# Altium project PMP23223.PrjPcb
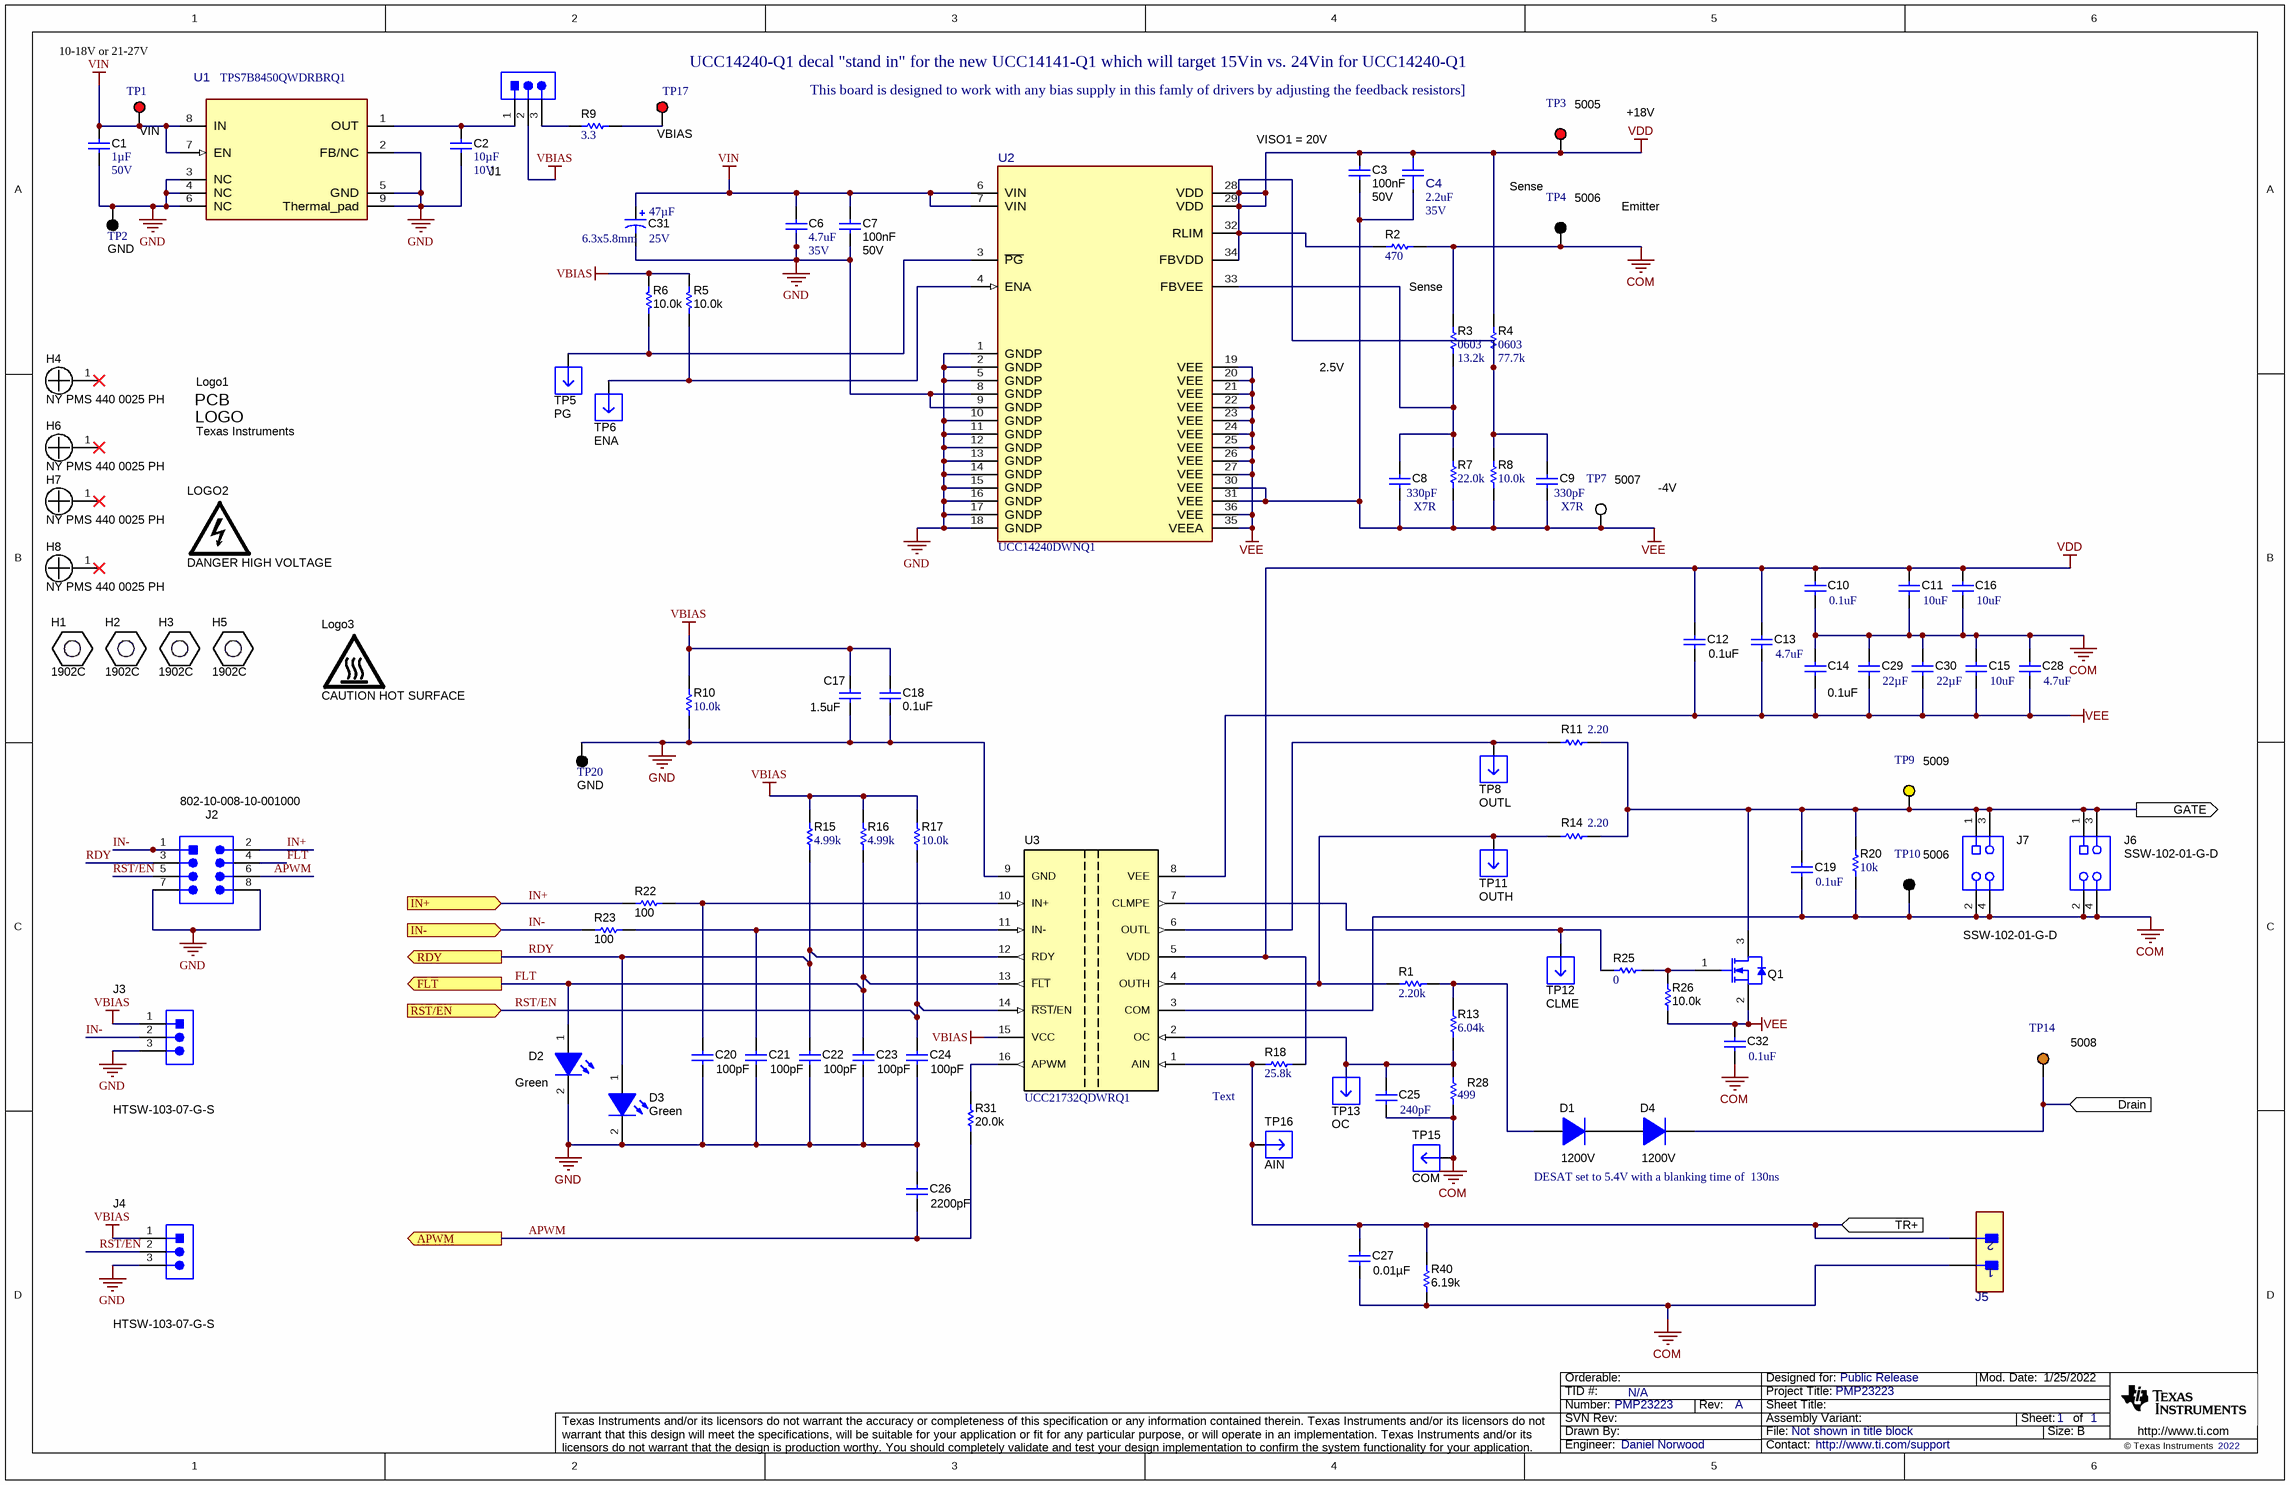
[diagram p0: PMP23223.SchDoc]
CopyrightYear: 2022; PCB_Layout: Daniel Norwood; PCB_Rev: E1; PRJ_Customer: Public Release; PRJ_Engineer: Daniel Norwood; PRJ_Number: PMP23223; PRJ_Title: PMP23223; SCH_Rev: A; TechSupport: http://www.ti.com/support; TID: N/A
2 sheets, 100 parts. Net scope: flat (ports and power ports of the same name join across sheets).
Board file: PMP23223.PcbDoc
Sheets:
  Block Diagram.SchDoc
  PMP23223.SchDoc

## Sheet Block Diagram.SchDoc
size A2; Date: Not shown in title block; ApprovedBy: Not shown in title block; CheckedBy: Not shown in title block; Author: Not shown in title block; CompanyName: Not shown in title block; Engineer: Not shown in title block; Organization: Not shown in title block; Address1: Not shown in title block; Address2: Not shown in title block; Address3: Not shown in title block; Address4: Not shown in title block; DocumentNumber: 1; Revision: Use project parameter SCH_Rev; SheetNumber: 2; SheetTotal: 2; PageSetup: Record=PageOptions¦CenterHorizontal=True¦CenterVertical=True¦PrintScale=0.69¦XCorrection=1.00¦YCorrection=1.00¦PrintKind=0¦BorderSize=5000000¦LeftOffset=0¦BottomOffset=0¦Orientation=2¦PaperLength=1000¦PaperWidth=1000¦Scale=100¦PaperSource=15¦PrintQuality=600¦MediaType=1¦DitherType=10¦PaperKind=Letter¦PrintScaleMode=1

## Sheet PMP23223.SchDoc
size 431 x 279 mm; Date: Not shown in title block; ApprovedBy: Not shown in title block; CheckedBy: Not shown in title block; Author: Not shown in title block; CompanyName: Not shown in title block; Engineer: Not shown in title block; Organization: Not shown in title block; Address1: Not shown in title block; Address2: Not shown in title block; Address3: Not shown in title block; Address4: Not shown in title block; DocumentNumber: 2; Revision: Use project parameter SCH_Rev; SheetNumber: 1; SheetTotal: 1; PageSetup: Record=PageOptions¦CenterHorizontal=True¦CenterVertical=True¦PrintScale=1.00¦XCorrection=1.00¦YCorrection=1.00¦PrintKind=0¦BorderSize=5000000¦LeftOffset=0¦BottomOffset=0¦Orientation=2¦PaperLength=1000¦PaperWidth=1000¦Scale=100¦PaperSource=15¦PrintQuality=600¦MediaType=1¦DitherType=10¦PaperKind=Letter¦PrintScaleMode=1

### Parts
C1  Cap_F: 1µF  VDC_V: 50V  [0805_HV]  (hidden comment: CGA4J3X7R1H105K125AB)
C2  Cap_F: 10µF  VDC_V: 10V  [0805_HV]  (hidden comment: GCJ21BR71A106KE01L)
C3  Cap_F: 100nF  VDC_V: 50V  [0603]  (hidden comment: CGA3E2X7R1H104K080AA)
C4  ValueDisplayed: 2.2uF  VDC_V: 35V  [FP-GRT188C8YA225KE13D_0603-MFG]  (hidden comment: GRT188C8YA225KE13D)
C6  ValueDisplayed: 4.7uF  VDC_V: 35V  [0805_HV]  (hidden comment: CGA4J1X7R1V475K125AC)
C7  Cap_F: 100nF  VDC_V: 50V  [0603]  (hidden comment: CGA3E2X7R1H104K080AA)
C8  TempCo: X7R  Cap_F: 330pF  [0603]  (hidden comment: GRM188R72A331KA01D)
C9  TempCo: X7R  Cap_F: 330pF  [0603]  (hidden comment: GRM188R72A331KA01D)
C10  ValueDisplayed: 0.1uF  [0402]  (hidden comment: GCM155R71C104KA55D)
C11  ValueDisplayed: 10uF  [1206_180]  (hidden comment: CL31B106KBHNNNE)
C12  ValueDisplayed: 0.1uF  [1206]  (hidden comment: C1206C104J5RACTU)
C13  ValueDisplayed: 4.7uF  [1206_180]  (hidden comment: C3216X7R1H475K160AC)
C14  ValueDisplayed: 0.1uF  [0402]  (hidden comment: GCM155R71C104KA55D)
C15  ValueDisplayed: 10uF  [1206_180]  (hidden comment: CL31B106KBHNNNE)
C16  ValueDisplayed: 10uF  [1206_180]  (hidden comment: CL31B106KBHNNNE)
C17  ValueDisplayed: 1.5uF  [0603]  (hidden comment: C1608X7R1A155K080AC)
C18  ValueDisplayed: 0.1uF  [0402]  (hidden comment: Capacitor)
C19  ValueDisplayed: 0.1uF  [0603]  (hidden comment: C1608X7R1H104K080AA)
C20  ValueDisplayed: 100pF  [0402]  (hidden comment: CC0402JRNPO9BN101)
C21  ValueDisplayed: 100pF  [0402]  (hidden comment: CC0402JRNPO9BN101)
C22  ValueDisplayed: 100pF  [0402]  (hidden comment: CC0402JRNPO9BN101)
C23  ValueDisplayed: 100pF  [0402]  (hidden comment: CC0402JRNPO9BN101)
C24  ValueDisplayed: 100pF  [0402]  (hidden comment: CC0402JRNPO9BN101)
C25  ValueDisplayed: 240pF  [0402]  (hidden comment: GRM1555C1H241JA01D)
C26  ValueDisplayed: 2200pF  [0402]  (hidden comment: GRM155R71C222KA01D)
C27  ValueDisplayed: 0.01µF  [0603]  (hidden comment: SR0603X7R103K1NT95(F)#M123A)
C28  ValueDisplayed: 4.7uF  [1206_180]  (hidden comment: C3216X7R1H475K160AC)
C29  ValueDisplayed: 22µF  [0805_HV]  (hidden comment: GRT21BR61E226ME13L)
C30  ValueDisplayed: 22µF  [0805_HV]  (hidden comment: GRT21BR61E226ME13L)
C31  Cap_Case: 6.3x5.8mm  VDC_V: 25V  ValueDisplayed: 47µF  [HXB_F61]  (hidden comment: HHXC250ARA470MF61G)
C32  ValueDisplayed: 0.1uF  [0603]  (hidden comment: CGA3E2X7R1H104K080AA)
D1  value 1200V  [SMA]  (hidden comment: STTH112A)
D2  value Green  [LG L29K_GREEN]  (hidden comment: LG L29K-G2J1-24-Z)
D3  value Green  [LG L29K_GREEN]  (hidden comment: LG L29K-G2J1-24-Z)
D4  value 1200V  [SMA]  (hidden comment: STTH112A)
H1  1902C  [Keystone_1902C]
H2  1902C  [Keystone_1902C]
H3  1902C  [Keystone_1902C]
H4  NY PMS 440 0025 PH  [NY PMS 440 0025 PH]
H5  1902C  [Keystone_1902C]
H6  NY PMS 440 0025 PH  [NY PMS 440 0025 PH]
H7  NY PMS 440 0025 PH  [NY PMS 440 0025 PH]
H8  NY PMS 440 0025 PH  [NY PMS 440 0025 PH]
J1  HTSW-103-07-G-S  [Samtec_HTSW-103-07-G-S]  (value not drawn)
J2  802-10-008-10-001000  [Mill-Max_802-10-008-10-001000]
J3  HTSW-103-07-G-S  [Samtec_HTSW-103-07-G-S]
J4  HTSW-103-07-G-S  [Samtec_HTSW-103-07-G-S]
J5  2011-1X02G00SB  [FP-2011-1X02G00SB_HDR-MFG]  (value not drawn)
J6  SSW-102-01-G-D  [Samtec_SSW-102-01-x-D]
J7  SSW-102-01-G-D  [Samtec_SSW-102-01-x-D]
Logo1  Texas Instruments  [TI_Symbol_Overlay_Small]  (no BOM)
LOGO2  DANGER HIGH VOLTAGE  [IEC_HighVoltage_Small]  (no BOM)
Logo3  CAUTION HOT SURFACE  [IEC_HotSurface_Small]  (no BOM)
Q1  SI2318CDS-T1-GE3  [SOT-23]  (value not drawn)
R1  ValueDisplayed: 2.20k  [0402]  (hidden comment: RMCF0402FT2K20)
R2  ValueDisplayed: 470  [0603]  (hidden comment: CRCW0603470RJNEA)
R3  ValueDisplayed: 13.2k  [0603]  (hidden comment: RT0603BRD0713K2L)
R4  ValueDisplayed: 77.7k  [0603]  (hidden comment: RT0603DRE0777K7L)
R5  ValueDisplayed: 10.0k  [0603]  (hidden comment: CRCW060310K0FKEA)
R6  ValueDisplayed: 10.0k  [0603]  (hidden comment: CRCW060310K0FKEA)
R7  ValueDisplayed: 22.0k  [0603]  (hidden comment: ERJ-3EKF2202V)
R8  ValueDisplayed: 10.0k  [0603]  (hidden comment: CRCW060310K0FKEA)
R9  ValueDisplayed: 3.3  [0402]  (hidden comment: CRCW04023R30JNED)
R10  ValueDisplayed: 10.0k  [0402]  (hidden comment: RMCF0402FT10K0)
R11  ValueDisplayed: 2.20  [1210]  (hidden comment: RC1210FR-072R2L)
R13  ValueDisplayed: 6.04k  [0402]  (hidden comment: CRCW04026K04FKED)
R14  ValueDisplayed: 2.20  [1210]  (hidden comment: RC1210FR-072R2L)
R15  ValueDisplayed: 4.99k  [0402]  (hidden comment: CRCW04024K99FKED)
R16  ValueDisplayed: 4.99k  [0402]  (hidden comment: CRCW04024K99FKED)
R17  ValueDisplayed: 10.0k  [0402]  (hidden comment: PCF0402-12-10KBT1)
R18  ValueDisplayed: 25.8k  [0603]  (hidden comment: RT0603DRE0725K8L)
R20  ValueDisplayed: 10k  [0603]  (hidden comment: CRCW060310K0JNEA)
R22  ValueDisplayed: 100  [0402]  (hidden comment: Resistor)
R23  ValueDisplayed: 100  [0402]  (hidden comment: Resistor)
R25  ValueDisplayed: 0  [0402]  (hidden comment: ERJ-2GE0R00X)
R26  ValueDisplayed: 10.0k  [0603]  (hidden comment: M55342K12B10E0T)
R28  ValueDisplayed: 499  [0402]  (hidden comment: CRCW0402499RFKED)
R31  ValueDisplayed: 20.0k  [0603]  (hidden comment: RT0603DRE0720KL)
R40  ValueDisplayed: 6.19k  [0603]  (hidden comment: CRCW06036K19FKEA)
TP1  VIN  [Keystone5005]
TP2  GND  [Keystone5006]
TP3  5005  [Keystone5005]
TP4  5006  [Keystone5006]
TP5  PG  [Mill-Max_0508-0-00-15-00-00-03-0]
TP6  ENA  [Mill-Max_0508-0-00-15-00-00-03-0]
TP7  5007  [Keystone5007]
TP8  OUTL  [Mill-Max_0508-0-00-15-00-00-03-0]
TP9  5009  [Keystone5009]
TP10  5006  [Keystone5006]
TP11  OUTH  [Mill-Max_0508-0-00-15-00-00-03-0]
TP12  CLME  [Mill-Max_0508-0-00-15-00-00-03-0]
TP13  OC  [Mill-Max_0508-0-00-15-00-00-03-0]
TP14  5008  [Keystone5008]
TP15  COM  [Mill-Max_0508-0-00-15-00-00-03-0]
TP16  AIN  [Mill-Max_0508-0-00-15-00-00-03-0]
TP17  VBIAS  [Keystone5005]
TP20  GND  [Keystone5006]
U1  TPS7B8450QWDRBRQ1  [DRB0008J-MFG]
U2  UCC14240DWNQ1  [DWN0036-MFG]
U3  UCC21732QDWRQ1  [DW0016B_HV]

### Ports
APWM (out), Drain (in), FLT (out), GATE (out), IN+ (in), IN- (in), RDY (out), RST/EN (in), TR+ (in)

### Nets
COM: C10.2 C11.2 C14.1 C15.1 C16.2 C19.2 C25.2 C27.2 C28.1 C29.1 C30.1 C32.2 J5.1 J6.2 J6.4 J7.2 J7.4 R2.1 R3.2 R20.1 R28.2 R40.1 TP4.1 TP10.1 TP15.1 U3.3(COM)
GND: C1.2 C2.2 C6.2 C7.2 C17.1 C18.2 C20.2 C21.2 C22.2 C23.2 C24.2 C26.2 C31.2(-) D2.2(K) D3.2(K) J2.7 J2.8 J3.3 J4.3 R10.1 TP2.1 TP20.1 U1.2(FB/NC) U1.3(NC) U1.4(NC) U1.5(GND) U1.6(NC) U1.9(Thermal_pad) U2.1(GNDP) U2.2(GNDP) U2.5(GNDP) U2.8(GNDP) U2.9(GNDP) U2.10(GNDP) U2.11(GNDP) U2.12(GNDP) U2.13(GNDP) U2.14(GNDP) U2.15(GNDP) U2.16(GNDP) U2.17(GNDP) U2.18(GNDP) U3.9(GND)
VBIAS: C17.2 C18.1 J1.2 J3.1 J4.1 R5.2 R6.1 R10.2 R15.2 R16.2 R17.2 U3.15(VCC)
VDD: C3.1 C4.2 C9.1 C10.1 C11.1 C12.1 C13.1 C16.1 R2.2 R4.1 R4.2 R8.2 R18.2 TP3.1 U2.28(VDD) U2.29(VDD) U2.32(RLIM) U2.34(FBVDD) U3.5(VDD)
VEE: C3.2 C4.1 C8.2 C9.2 C12.2 C13.2 C14.2 C15.2 C28.2 C29.2 C30.2 C32.1 Q1.2(S) R7.1 R8.1 R26.1 TP7.1 U2.19(VEE) U2.20(VEE) U2.21(VEE) U2.22(VEE) U2.23(VEE) U2.24(VEE) U2.25(VEE) U2.26(VEE) U2.27(VEE) U2.30(VEE) U2.31(VEE) U2.35(VEEA) U2.36(VEE) U3.8(VEE)
VIN: C1.1 C6.1 C7.1 C31.1(+) TP1.1 U1.7(EN) U1.8(IN) U2.6(VIN) U2.7(VIN)
APWM: C26.1 J2.6 R31.2 ; port APWM
Drain: D4.1(K) TP14.1 ; port Drain
FLT: C23.1 D2.1(A) J2.4 R16.1 U3.13(~{FLT}) ; port FLT
GATE: C19.1 J6.1 J6.3 J7.1 J7.3 Q1.3(D) R11.2 R14.2 R20.2 TP9.1 ; port GATE
IN+: J2.2 R22.2 ; port IN+
IN-: J2.1 J3.2 R23.2 ; port IN-
RDY: C22.1 D3.1(A) J2.3 R15.1 U3.12(RDY) ; port RDY
RST/EN: C24.1 J2.5 J4.2 R17.1 U3.14(~{RST}/EN) ; port RST/EN
TR+: C27.1 J5.2 R18.1 R40.2 TP16.1 U3.1(AIN) ; port TR+
NetC2_1: C2.1 J1.1 U1.1(OUT)
NetC8_1: C8.1 R3.1 R7.2 U2.33(FBVEE)
NetC20_1: C20.1 R22.1 U3.10(IN+)
NetC21_1: C21.1 R23.1 U3.11(IN-)
NetC25_1: C25.1 R13.2 R28.1 TP13.1 U3.2(OC)
NetD1_1: D1.1(K) D4.2(A)
NetD1_2: D1.2(A) R1.2 R13.1
NetJ1_3: J1.3 R9.2
NetQ1_1: Q1.1(G) R25.1 R26.2
NetR1_1: R1.1 R14.1 TP11.1 U3.4(OUTH)
NetR5_1: R5.1 TP6.1 U2.4(ENA)
NetR6_2: R6.2 TP5.1 U2.3(~{PG})
NetR9_1: R9.1 TP17.1
NetR11_1: R11.1 TP8.1 U3.6(OUTL)
NetR25_2: R25.2 TP12.1 U3.7(CLMPE)
NetR31_1: R31.1 U3.16(APWM)

Not connected (* = marked no-connect by the designer): H4 1*; H6 1*; H7 1*; H8 1*

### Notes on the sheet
- 10-18V or 21-27V
- UCC14240-Q1 decal "stand in" for the new UCC14141-Q1 which will target 15Vin vs. 24Vin for UCC14240-Q1
- This board is designed to work with any bias supply in this famly of drivers by adjusting the feedback resistors]
- (near C3) VISO1 = 20V
- +18V
- Sense
- Emitter
- 2.5V
- -4V
- Text
- DESAT set to 5.4V with a blanking time of  130ns

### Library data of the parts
C1 = CMP-0007976-2: CAP, CERM, 1 uF, 50 V, +/- 10%, X7R, AEC-Q200 Grade 1, 0805; Manufacturer: TDK; TaMin_C: -55°C; Polarized: N; SizeAreaWB_mm2: 6.75; Value1: 0.008782 ohm; U/M: EA; Value: 1uF; TaMax_C: 125°C; SizeZ_mm: 1.45; SizeX_mm: 2; SizeY_mm: 1.25; Cap_Case: 0805; SizeArea_mm2: 2.5; AEC Qualified: Y; AEC Grade: 1; AEC Category: Q200; ESR_ohm: 8.782m; IRMS_A: 2.2049A
C2 = CMP-0079153-1: CAP, CERM, 10 µF, 10 V,+/- 10%, X7R, AEC-Q200 Grade 1, 0805; Manufacturer: MuRata; SizeAreaWB_mm2: 6.75; SizeArea_mm2: 2.5; AEC Qualified: Y; AEC Category: Q200; Value: 10uF; TaMax_C: 125°C; SizeZ_mm: 1.45; AEC Grade: 1; Polarized: N; TaMin_C: -55°C; SizeY_mm: 1.25; U/M: EA; SizeX_mm: 2; Cap_Case: 0805
C3 C7 = CMP-0007078-4: CAP, CERM, 0.1 uF, 50 V, +/- 10%, X7R, AEC-Q200 Grade 1, 0603; Manufacturer: TDK; TaMin_C: -55°C; ESR_ohm: 0.0296; Polarized: N; SizeAreaWB_mm2: 4.68; Value1: 0.0296 ohm; U/M: EA; Value: 0.1uF; TaMax_C: 125°C; SizeZ_mm: 1; SizeX_mm: 1.6; SizeY_mm: 0.8; SizeArea_mm2: 1.28; AEC Qualified: Y; IRMS_A: 971.99mA; AEC Category: Q200
C4 = CMP-0090212-1: 2.2µF ±10% 35V Ceramic Capacitor X6S 0603 (1608 Metric); Manufacturer: Murata; TempCo: 22%; SizeZ_mm: 1mm; AEC Qualified: Yes; AEC Grade: Grade 2
C6 = CMP-0007964-2: CAP, CERM, 4.7 uF, 35 V, +/- 10%, X7R, AEC-Q200 Grade 1, 0805; Manufacturer: TDK; Value: 4.7uF; SizeZ_mm: 1.45; Cap_F: 4.7µF; AEC Qualified: Y; AEC Grade: 1; TaMin_C: -55°C; ESR_ohm: 2.346m; Polarized: N; SizeAreaWB_mm2: 6.75; Value1: 0.002346 ohm; U/M: EA; TaMax_C: 125°C; SizeX_mm: 2; SizeY_mm: 1.25; Cap_Case: 0805; SizeArea_mm2: 2.5; IRMS_A: 4.2602A; AEC Category: Q200
C8 C9 = CMP-0007478-4: CAP, CERM, 330 pF, 100 V, +/- 10%, X7R, 0603; Manufacturer: MuRata; TaMin_C: -55°C; Polarized: N; SizeAreaWB_mm2: 4.68; Value1: Unknown; U/M: EA; Value: 330pF; TaMax_C: 125°C; SizeZ_mm: 1; SizeX_mm: 1.6; SizeY_mm: 0.8; Value2: 100V; SizeArea_mm2: 1.28; AEC Category: Q200
C10 = CMP-0006351-2: CAP, CERM, 0.1 uF, 16 V, +/- 10%, X7R, 0402; Manufacturer: MuRata; TaMin_C: -55°C; Polarized: N; SizeAreaWB_mm2: 3; Value1: Unknown; U/M: EA; Value: 0.1uF; TaMax_C: 125°C; SizeZ_mm: 0.6; SizeX_mm: 1; SizeY_mm: 0.5; Value2: 16V; Cap_F: 100nF; AEC Category: Q200
C11 C15 C16 = CMP-0008802-2: CAP, CERM, 10 uF, 50 V, +/- 10%, X7R, 1206; Manufacturer: Samsung; TaMin_C: -55°C; Polarized: N; SizeAreaWB_mm2: 10.92; Value1: Unknown; U/M: EA; Value: 10uF; TaMax_C: 125°C; SizeZ_mm: 1.8; SizeX_mm: 3.2; SizeY_mm: 1.6; Cap_Case: 1206; Value2: 50V; SizeArea_mm2: 5.12; Cap_F: 10µF; AEC Category: Q200
C12 = CMP-0008584-2: CAP, CERM, 0.1 uF, 50 V, +/- 5%, X7R, 1206; Manufacturer: Kemet; TaMin_C: -55°C; ESR_ohm: 0.059; Polarized: N; SizeAreaWB_mm2: 10.92; Value1: 0.059 ohm; U/M: EA; Value: 0.1uF; TaMax_C: 125°C; SizeZ_mm: 1.35; SizeX_mm: 3.2; SizeY_mm: 1.6; Value2: 50V; SizeArea_mm2: 5.12; Cap_F: 100nF; IRMS_A: 1.2A; AEC Category: Q200
C13 C28 = CMP-0008702-2: CAP, CERM, 4.7 uF, 50 V, +/- 10%, X7R, 1206; Manufacturer: TDK; TaMin_C: -55°C; ESR_ohm: 3.158m; Polarized: N; SizeAreaWB_mm2: 10.92; Value1: 0.003158 ohm; U/M: EA; Value: 4.7uF; TaMax_C: 125°C; SizeZ_mm: 1.8; SizeX_mm: 3.2; SizeY_mm: 1.6; Value2: 50V; SizeArea_mm2: 5.12; Cap_F: 4.7µF; IRMS_A: 4.0838A; AEC Category: Q200
C14 = CMP-0006351-2: CAP, CERM, 0.1 uF, 16 V, +/- 10%, X7R, 0402; Manufacturer: MuRata; TaMin_C: -55°C; Polarized: N; SizeAreaWB_mm2: 3; Value1: Unknown; U/M: EA; Value: 0.1uF; TaMax_C: 125°C; SizeZ_mm: 0.6; SizeX_mm: 1; SizeY_mm: 0.5; Value2: 16V; CompType: Capacitor; Cap_F: 100nF; AEC Category: Q200
C17 = CMP-0007035-4: CAP, CERM, 1.5 uF, 10 V, +/- 10%, X7R, 0603; Manufacturer: TDK; TaMin_C: -55°C; ESR_ohm: 4.327m; Polarized: N; SizeAreaWB_mm2: 4.68; Value1: 0.004327 ohm; U/M: EA; Value: 1.5uF; TaMax_C: 125°C; SizeZ_mm: 1; SizeX_mm: 1.6; SizeY_mm: 0.8; Value2: 10V; SizeArea_mm2: 1.28; CompType: Capacitor; Cap_F: 1.5µF; IRMS_A: 2.50174A; AEC Category: Q200
C18 = CMP-0006659-2: CAP, CERM, 0.1 uF, 25 V, +/- 10%, X7R, 0402; PartNumber: GRM155R71E104KE14D; Manufacturer: MuRata; Polarized: N; Value: 0.1uF; U/M: EA; Cap_F: 100nF; Value1: Unknown; VDC_V: 25V; TaMin_C: -55°C; TaMax_C: 125°C; SizeArea_mm2: 0.5; SizeAreaWB_mm2: 3; SizeX_mm: 1; SizeZ_mm: 0.6; AEC Category: Q200
C19 = CMP-0007044-5: CAP, CERM, 0.1 uF, 50 V, +/- 10%, X7R, 0603; Manufacturer: TDK; TaMin_C: -55°C; Polarized: N; SizeAreaWB_mm2: 4.68; Value1: 0.0296 ohm; U/M: EA; Value: 0.1uF; TaMax_C: 125°C; SizeZ_mm: 1; SizeX_mm: 1.6; SizeY_mm: 0.8; Value2: 50V; SizeArea_mm2: 1.28; Cap_F: 100nF; AEC Category: Q200; ESR_ohm: 29.6m; IRMS_A: 971.99mA
C20-C24 = CMP-0006303-2: CAP, CERM, 100 pF, 50 V, +/- 5%, C0G/NP0, 0402; Manufacturer: Yageo America; TaMin_C: -55°C; Polarized: N; SizeAreaWB_mm2: 3; Value1: Unknown; U/M: EA; Value: 100pF; TaMax_C: 125°C; SizeZ_mm: 0.6; SizeX_mm: 1; SizeY_mm: 0.5; Value2: 50V; CompType: Capacitor; AEC Category: Q200
C25 = CMP-0006442-2: CAP, CERM, 240 pF, 50 V, +/- 5%, C0G/NP0, 0402; Manufacturer: MuRata; TaMin_C: -55°C; Polarized: N; SizeAreaWB_mm2: 3; Value1: Unknown; U/M: EA; Value: 240pF; TaMax_C: 125°C; SizeZ_mm: 0.6; SizeX_mm: 1; SizeY_mm: 0.5; Value2: 50V; AEC Category: Q200
C26 = CMP-0006646-2: CAP, CERM, 2200 pF, 16 V, +/- 10%, X7R, 0402; Manufacturer: MuRata; TaMin_C: -55°C; Polarized: N; SizeAreaWB_mm2: 3; Value1: Unknown; U/M: EA; Value: 2200pF; TaMax_C: 125°C; SizeZ_mm: 0.6; SizeX_mm: 1; SizeY_mm: 0.5; Value2: 16V; Cap_F: 2.2nF; AEC Category: Q200
C27 = CMP-0079721-1: CAP, CERM, 0.01 µF, 25 V,+/- 10%, X7R, 0603; Manufacturer: Presidio Components; TaMin_C: -55°C; Polarized: N; SizeAreaWB_mm2: 4.68; U/M: EA; Value: 0.01uF; TaMax_C: 125°C; SizeZ_mm: 1; SizeX_mm: 1.6; SizeY_mm: 0.8; Value2: 25V; SizeArea_mm2: 1.28; CompType: Capacitor; Cap_F: 10nF; AEC Category: Q200
C29 C30 = CMP-0084680-1: CAP, CERM, 22 µF, 25 V,+/- 20%, X5R, AEC-Q200 Grade 3, 0805; Manufacturer: MuRata; TaMin_C: -55°C; Polarized: N; SizeAreaWB_mm2: 6.75; U/M: EA; Value: 22uF; TaMax_C: 85°C; SizeZ_mm: 1.45; SizeX_mm: 2; SizeY_mm: 1.25; Cap_Case: 0805; Value2: 25V; SizeArea_mm2: 2.5; AEC Qualified: Y; AEC Category: Q200; AEC Grade: 3
C31 = CMP-0750159-1: CAP, AL, 47 µF, 25 V, +/- 20%, 0.05 ohm, AEC-Q200 Grade 1, SMD; Manufacturer: Chemi-Con; TaMin_C: -55°C; Polarized: Y; Value: 47uF; TaMax_C: 125°C; CompType: Capacitor; AEC Grade: 1; AEC Category: Q200; ESR_ohm: 50m; U/M: EA
C32 = CMP-0007078-4: CAP, CERM, 0.1 uF, 50 V, +/- 10%, X7R, AEC-Q200 Grade 1, 0603; Manufacturer: TDK; TaMin_C: -55°C; ESR_ohm: 29.6m; Polarized: N; SizeAreaWB_mm2: 4.68; Value1: 0.0296 ohm; U/M: EA; Value: 0.1uF; TaMax_C: 125°C; SizeZ_mm: 1; SizeX_mm: 1.6; SizeY_mm: 0.8; Value2: 50V; SizeArea_mm2: 1.28; AEC Qualified: Y; Cap_F: 100nF; IRMS_A: 971.99mA; AEC Category: Q200
D1 D4 = CMP-0077081-1: Diode, Ultrafast, 1200 V, 1 A, SMA; Manufacturer: STMicroelectronics; SizeAreaWB_mm2: 37.3428; Vr_V: 1.2kV; SizeArea_mm2: 16.3228; AEC Qualified: N; TJmax_C: 175°C; AEC Category: Q101; SizeZ_mm: 2.87; Green_REACh: Incomplete; Io_A: 1A; Vf_V: 1.9V; SizeY_mm: 2.92; Green_Lifecycle: Not Set; U/M: EA; SizeX_mm: 5.59
D2 D3 = CMP-0002874-1: LED, Green, SMD; Manufacturer: OSRAM; Io_A: 2mA; Tjmax_C: 110°C; Value1: W; U/M: EA; Vf_V: 1.7V
H1-H3 H5 = CMP-0003610-1: Standoff, Hex, 0.5"L #4-40 Nylon; Manufacturer: Keystone; CompType: Hardware
H4 H6-H8 = CMP-0003617-1: Machine Screw, Round, #4-40 x 1/4, Nylon, Philips panhead; Manufacturer: B&F Fastener Supply; CompType: Hardware
J1 J3 J4 = CMP-0075484-1: Header, 100mil, 3x1, Gold, TH; Manufacturer: Samtec; Green_REACh: Passed; CT: False; Green_Lifecycle: Active; CNHeader: True
J2 = CMP-0055096-2: Header, 2.54 mm, 4x2, Gold, TH; Manufacturer: Mill-Max; Gender: Male; Row_Count: 2; Pitch_mm: 2.54; Shrouded: N
J5 = CMP-0092598-1: Manufacturer: Oupiin; DUT-Pitch_mm: 2.54mm; Row_Count: 1; SizeZ_mm: 9.1mm; Conn Orientation: Straight; AEC Qualified: No; Current_A: 3A; ContactFinish: Gold,Nickel; Conn Gender: Male; Voltage_V: 150V
J6 J7 = CMP-0055713-1: Receptacle, 2.54mm, 2x2, Gold, TH; Manufacturer: Samtec; Pitch_mm: 2.54; Gender: Female; Cert_CSA: Y; Voltage_V: 465V; Current_A: 4.7A; CT: TRUE; Row_Count: 2; CompType: Socket Strip; CNHeader: FALSE
Logo1 = CMP-0074838-1: Texas Instrument Corporate Signature; SymbolCreator: a0412235; Lib Reference: TI_Logo
LOGO2 = CMP-0074835-1: IEC 61010-1 High Voltage Warning; SymbolCreator: a0412235
Logo3 = CMP-0074837-2: IEC 61010-1 Hot Surface Warning; Manufacturer: Texas Instruments; CompType: IC; AEC Category: Q200; SymbolCreator: a0412235
Q1 = CMP-0000739-1: MOSFET, N-CH, 40 V, 5.6 A, SOT-23; Alternate Manufacturer: None; Manufacturer: Vishay-Siliconix; SizeZ_mm: 1.1; ChType: N; Value2: 5.8 nC; Value1: 0.05; VdsMax_V: 40V; SizeX_mm: 2.5; SizeY_mm: 3; Vgs_V: 20V; Value: 40V; Rdson45_ohm: 0.051; SizeArea_mm2: 7.5; AEC Category: Q101; IdsMax_A: 5.6A; SizeAreaWB_mm2: 14; U/M: EA; QgTyp_nC: 5.8
R1 = CMP-0026758-1: RES, 2.20 k, 1%, 0.063 W, AEC-Q200 Grade 0, 0402; Manufacturer: Stackpole Electronics Inc; Power_W: 63mW; TempCo: 100 ppm/C; Value_Code: 2k20; Value: 2.20k; Res_ohm: 2.2k; SizeX_mm: 1; SizeY_mm: 0.5; SizeZ_mm: 0.6; Value2: 0.063W; AEC Qualified: Y; AEC Grade: 0; AEC Category: Q200; VDC_V: 50V; U/M: EA
R2 = CMP-0025813-4: RES, 470, 5%, 0.1 W, AEC-Q200 Grade 0, 0603; Manufacturer: Vishay-Dale; Power_W: 100mW; TempCo: 200 ppm/C; Value_Code: 470R; Value: 470; EIA_Code: E24; SizeX_mm: 1.6; SizeY_mm: 0.8; SizeZ_mm: 1; Value2: 0.1W; SizeArea_mm2: 1.28; AEC Qualified: Y; VDC_V: 75V; AEC Category: Q200; AEC Grade: 0
R3 = CMP-0023730-2: RES, 13.2 k, 0.1%, 0.1 W, 0603; Manufacturer: Yageo America; Power_W: 100mW; TempCo: 25 ppm/C; Value_Code: 13k2; Value: 13.2k; EIA_Code: E192; SizeX_mm: 1.6; SizeY_mm: 0.8; SizeZ_mm: 1; Value2: 0.1W; SizeArea_mm2: 1.28; VDC_V: 75V; AEC Category: Q200; U/M: EA
R4 = CMP-0025564-2: RES, 77.7 k, 0.5%, 0.1 W, 0603; Manufacturer: Yageo America; Power_W: 100mW; TempCo: 50 ppm/C; Value_Code: 77k7; Value: 77.7k; EIA_Code: E192; SizeX_mm: 1.6; SizeY_mm: 0.8; SizeZ_mm: 1; Value2: 0.1W; SizeArea_mm2: 1.28; VDC_V: 75V; AEC Category: Q200; U/M: EA
R5 R6 R8 = CMP-0021998-4: RES, 10.0 k, 1%, 0.1 W, AEC-Q200 Grade 0, 0603; Manufacturer: Vishay-Dale; Power_W: 100mW; TempCo: 100 ppm/C; Value_Code: 10k0; Value: 10.0k; EIA_Code: E96; Res_ohm: 10k; SizeX_mm: 1.6; SizeY_mm: 0.8; SizeZ_mm: 1; Value2: 0.1W; SizeArea_mm2: 1.28; AEC Qualified: Y; VDC_V: 75V; AEC Category: Q200; AEC Grade: 0
R7 = CMP-0022692-3: RES, 22.0 k, 1%, 0.1 W, AEC-Q200 Grade 0, 0603; Manufacturer: Panasonic; Power_W: 100mW; TempCo: 100 ppm/C; Value_Code: 22k0; Value: 22.0k; Res_ohm: 22k; SizeX_mm: 1.6; SizeY_mm: 0.8; SizeZ_mm: 1; Value2: 0.1W; SizeArea_mm2: 1.28; AEC Qualified: Y; VDC_V: 50V; AEC Category: Q200; AEC Grade: 0; U/M: EA
R9 = CMP-0026926-3: RES, 3.3, 5%, 0.063 W, AEC-Q200 Grade 0, 0402; Manufacturer: Vishay-Dale; Power_W: 63mW; TempCo: 200 ppm/C; Value_Code: 3R30; Value: 3.3; EIA_Code: E24; SizeX_mm: 1; SizeY_mm: 0.5; SizeZ_mm: 0.6; Value2: 0.063W; AEC Qualified: Y; VDC_V: 50V; AEC Grade: 0; AEC Category: Q200
R10 = CMP-0026754-1: RES, 10.0 k, 1%, 0.063 W, AEC-Q200 Grade 0, 0402; Manufacturer: Stackpole Electronics Inc; Power_W: 63mW; TempCo: 100 ppm/C; Value_Code: 10k0; Value: 10.0k; EIA_Code: E96; Res_ohm: 10k; SizeX_mm: 1; SizeY_mm: 0.5; SizeZ_mm: 0.6; Value2: 0.063W; AEC Qualified: Y; VDC_V: 50V; AEC Grade: 0; AEC Category: Q200; U/M: EA
R11 R14 = CMP-0083047-1: RES, 2.20, 1%, 0.5 W, 1210; Manufacturer: Yageo; Power_W: 500mW; TempCo: 200 ppm/C; Value_Code: 2R20; Value: 2.20; Res_ohm: 2.2; SizeX_mm: 3.2; SizeY_mm: 2.5; SizeZ_mm: 1.35; Value2: 0.5W; SizeArea_mm2: 8; AEC Qualified: N; VDC_V: 200V; AEC Category: Q200; SizeAreaWB_mm2: 14.7
R13 = CMP-0026512-2: RES, 6.04 k, 1%, 0.063 W, AEC-Q200 Grade 0, 0402; Manufacturer: Vishay-Dale; Power_W: 63mW; TempCo: 100 ppm/C; Value_Code: 6k04; Value: 6.04k; SizeX_mm: 1; SizeY_mm: 0.5; SizeZ_mm: 0.6; Value2: 0.063W; AEC Qualified: Y; AEC Grade: 0; AEC Category: Q200; EIA_Code: E96; VDC_V: 50V
R15 R16 = CMP-0026414-2: RES, 4.99 k, 1%, 0.063 W, AEC-Q200 Grade 0, 0402; Manufacturer: Vishay-Dale; Power_W: 63mW; TempCo: 100 ppm/C; Value_Code: 4k99; Value: 4.99k; EIA_Code: E96; SizeX_mm: 1; SizeY_mm: 0.5; SizeZ_mm: 0.6; Value2: 0.063W; AEC Qualified: Y; VDC_V: 50V; AEC Category: Q200; AEC Grade: 0
R17 = CMP-0026797-1: RES, 10.0 k, 0.1%, 0.063 W, 0402; Manufacturer: TT Electronics/IRC; Power_W: 63mW; TempCo: 10 ppm/C; Value_Code: 10k0; U/M: EA; Value: 10.0k; EIA_Code: E192; Res_ohm: 10k; SizeX_mm: 1; SizeY_mm: 0.5; SizeZ_mm: 0.6; Value2: 0.063W; VDC_V: 25V; AEC Category: Q200
R18 = CMP-0024995-2: RES, 25.8 k, 0.5%, 0.1 W, 0603; Manufacturer: Yageo America; Power_W: 100mW; TempCo: 50 ppm/C; Value_Code: 25k8; U/M: EA; Value: 25.8k; SizeX_mm: 1.6; SizeY_mm: 0.8; SizeZ_mm: 1; Value2: 0.1W; SizeArea_mm2: 1.28; AEC Category: Q200; EIA_Code: E192; VDC_V: 75V
R20 = CMP-0025701-4: RES, 10 k, 5%, 0.1 W, AEC-Q200 Grade 0, 0603; Manufacturer: Vishay-Dale; Power_W: 100mW; TempCo: 200 ppm/C; Value_Code: 10k0; Value: 10k; EIA_Code: E24; SizeX_mm: 1.6; SizeY_mm: 0.8; SizeZ_mm: 1; Value2: 0.1W; SizeArea_mm2: 1.28; AEC Qualified: Y; VDC_V: 75V; AEC Category: Q200; AEC Grade: 0
R22 R23 = CMP-0025951-2: RES, 100, 1%, 0.063 W, 0402; PartNumber: CRCW0402100RFKED; Manufacturer: Vishay-Dale; Value: 100; Value_Code: 100R; Power_W: 63mW; Value2: 0.063W; VDC_V: 50V; TempCo: 100 ppm/C; SizeArea_mm2: 0.5; SizeX_mm: 1; SizeZ_mm: 0.6; EIA_Code: E96; U/M: EA; AEC Category: Q200
R25 = CMP-0026992-3: RES, 0, 5%, 0.1 W, AEC-Q200 Grade 0, 0402; Manufacturer: Panasonic; Power_W: 100mW; TempCo: 600 ppm/C; Value_Code: 0000; Value: 0; EIA_Code: E24; SizeX_mm: 1; SizeY_mm: 0.5; SizeZ_mm: 0.6; Value2: 0.1W; AEC Qualified: Y; VDC_V: 50V; AEC Category: Q200; SizeAreaWB_mm2: 3
R26 = CMP-0080488-1: RES, 10.0 k, 1%, 0.1 W, 0603; Manufacturer: TT Electronics/IRC; Power_W: 100mW; TempCo: 100 ppm/C; SizeAreaWB_mm2: 4.68; Value_Code: 10k0; Value: 10.0k; EIA_Code: E96; Res_ohm: 10k; SizeX_mm: 1.6; SizeY_mm: 0.8; SizeZ_mm: 1; Value2: 0.1W; SizeArea_mm2: 1.28; AEC Qualified: N; AEC Category: Q200
R28 = CMP-0026402-2: RES, 499, 1%, 0.063 W, AEC-Q200 Grade 0, 0402; Manufacturer: Vishay-Dale; Power_W: 63mW; TempCo: 100 ppm/C; Value_Code: 499R; Value: 499; SizeX_mm: 1; SizeY_mm: 0.5; SizeZ_mm: 0.6; Value2: 0.063W; AEC Qualified: Y; AEC Grade: 0; AEC Category: Q200; EIA_Code: E96; VDC_V: 50V
R31 = CMP-0024922-3: RES, 20.0 k, 0.5%, 0.1 W, 0603; Manufacturer: Yageo America; Power_W: 100mW; TempCo: 50 ppm/C; Value_Code: 20k0; U/M: EA; Value: 20.0k; EIA_Code: E192; Res_ohm: 20k; SizeX_mm: 1.6; SizeY_mm: 0.8; SizeZ_mm: 1; Value2: 0.1W; SizeArea_mm2: 1.28; CompType: Resistor; VDC_V: 75V; AEC Category: Q200
R40 = CMP-0022559-4: RES, 6.19 k, 1%, 0.1 W, AEC-Q200 Grade 0, 0603; Manufacturer: Vishay-Dale; Power_W: 100mW; TempCo: 100 ppm/C; Value_Code: 6k19; Value: 6.19k; EIA_Code: E96; SizeX_mm: 1.6; SizeY_mm: 0.8; SizeZ_mm: 1; Value2: 0.1W; SizeArea_mm2: 1.28; CompType: Resistor; AEC Qualified: Y; VDC_V: 75V; AEC Category: Q200; AEC Grade: 0
TP1 TP17 = CMP-0055142-2: Test Point, Compact, Red, TH; Manufacturer: Keystone Electronics; Green_REACh: Passed; CT: TRUE; ContactFinish: Silver; CNHeader: FALSE; Green_Lifecycle: Active
TP2 TP20 = CMP-0055143-2: Test Point, Compact, Black, TH; Manufacturer: Keystone Electronics; ContactFinish: Silver; Green_Lifecycle: Active; Green_REACh: Passed; CT: TRUE; CNHeader: FALSE
TP3 = CMP-0055142-2: Test Point, Compact, Red, TH; Manufacturer: Keystone Electronics; CNHeader: FALSE; ContactFinish: Silver; CT: TRUE; Green_Lifecycle: Active; Green_REACh: Passed
TP4 TP10 = CMP-0055143-2: Test Point, Compact, Black, TH; Manufacturer: Keystone Electronics; CNHeader: FALSE; ContactFinish: Silver; CT: TRUE; Green_Lifecycle: Active; Green_REACh: Passed
TP5 TP6 TP8 TP11-TP13 TP15 TP16 = CMP-0055027-1: PCB Pin, 20mil Dia, Gold, TH; Manufacturer: Mill-Max; PartNumber: 0508-0-00-15-00-00-03-0; CNHeader: FALSE; Gender: Male; CompType: PCB Pin
TP7 = CMP-0055144-2: Test Point, Compact, White, TH; Manufacturer: Keystone Electronics; CNHeader: FALSE; ContactFinish: Silver; CT: TRUE; Green_Lifecycle: Active; Green_REACh: Passed
TP9 = CMP-0055146-2: Test Point, Compact, Yellow, TH; Manufacturer: Keystone Electronics; CNHeader: FALSE; ContactFinish: Silver; CT: TRUE; Green_Lifecycle: Active; Green_REACh: Passed
TP14 = CMP-0055145-2: Test Point, Compact, Orange, TH; Manufacturer: Keystone Electronics; CNHeader: FALSE; ContactFinish: Silver; CT: TRUE; Green_Lifecycle: Active; Green_REACh: Passed
U1 = CMP-0095031-1: Linear Voltage Regulator IC Positive Fixed 1 Output 150mA 8-SON (3x3); Manufacturer: Texas Instruments; SizeZ_mm: 1mm; AEC Qualified: Yes; AEC Grade: Grade 1; Number Of Outputs: 1; Standoff Height: 0mm; Output Voltage: 5V; TJmax_C: +150°C; Dropout Voltage: 155mV; TaMax_C: +125°C; Accuracy Percentage: 0.75%; Min Supply Voltage: 5.155V; Max Supply Voltage: 40V; TaMin_C: -40°C; Nominal Supply Current: 18uA
U2 = CMP-0089786-7: 2W, 24V-Vin, 25V-Vout, High-Efficiency, >2. 5 kVRMS Isolated DC-DC Converter; Manufacturer: Texas Instruments; Max Supply Voltage: 27V; Standoff Height: 0.1mm; SizeZ_mm: 3.55mm; AEC Qualified: Yes; Output Voltage: 18-25/2.5-25V; TaMin_C: -40°C; CompType: IC; TJmax_C: +150°C; Min Supply Voltage: 21V; AEC Grade: Grade 1; Number Of Outputs: 2; Output Type: AdjustableProgrammable; TaMax_C: +125°C; AEC Category: Q200
U3 = CMP-0080536-2: Single Channel Isolated Gate Driver for SiC/IGBT with Advanced Protection and High-CMTI, DW0016B (SOIC-16); Alternate PartNumber: UCC21732QDWQ1; Manufacturer: Texas Instruments; AEC Qualified: Y; AEC Category: Q200; CompType: IC; SizeArea_mm2: 107.12; SizeY_mm: 10.3; SizeZ_mm: 2.65; SizeX_mm: 10.4; SizeAreaWB_mm2: 152.52

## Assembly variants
001: not fitted C15 C16 R1 R18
